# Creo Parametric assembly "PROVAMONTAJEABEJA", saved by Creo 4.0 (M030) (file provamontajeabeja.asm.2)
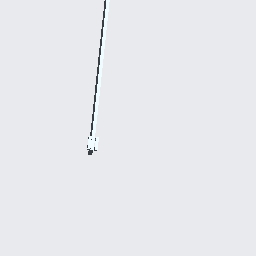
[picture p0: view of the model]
Units: millimeter Newton Second (mmNs); MM, TONNE, SECS

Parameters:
  MODELED_BY = "aj"

Created from: MMNS_ASM_DESIGN.ASM

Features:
  1. datum plane "ASM_RIGHT"
  2. datum plane "ASM_TOP"
  3. datum plane "ASM_FRONT"
  4. coordinate system
  5. component "RAMPA"
  6. component "MONTAJEABEJA"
